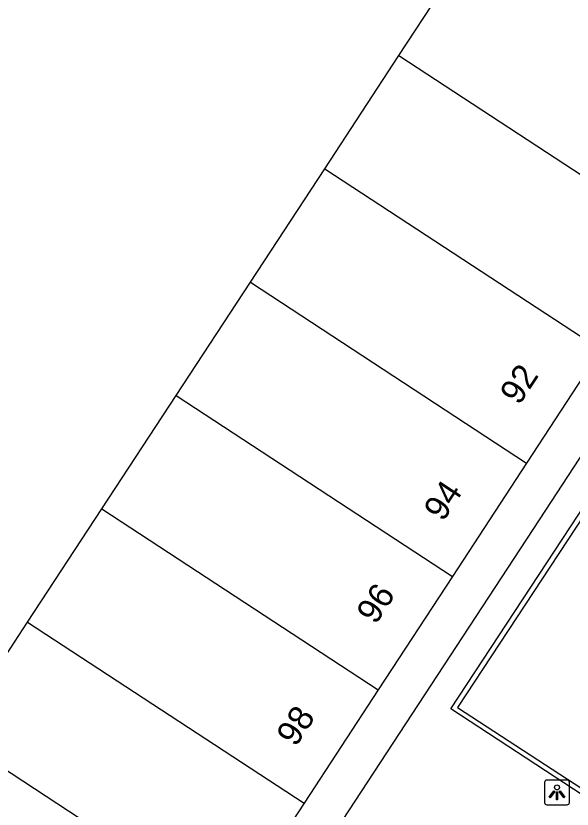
# Model space of a CAD drawing. Extents: x 155640 to 156810, y 382822 to 384046.
# Drawn here: x 156426.7 to 156449.06, y 383730.47 to 383762.35 of the extents above; entities that cross this region are included whole.
import ezdxf

# ---------------------------------------------------------------- set-up
doc = ezdxf.new("R2010")
doc.units = 0
for name, color, linetype in [('IMGEO_Lichtpunt', 7, 'Continuous'), ('IMGEO_Lijnafwatering', 7, 'Continuous'), ('IMGEO_Muur', 7, 'Continuous'), ('IMGEO_Pand', 7, 'Continuous'), ('IMGEO_Pand_nummerreeks', 7, 'Continuous')]:
    doc.layers.add(name, color=color, linetype=linetype)

msp = doc.modelspace()

# ---------------------------------------------------------------- linework, layer by layer
at = {"layer": 'IMGEO_Lichtpunt'}
for p, q in [((156447.949, 383731.548), (156447.949, 383730.741)), ((156447.949, 383731.548), (156447.949, 383730.741)), ((156448.851, 383731.643), (156448.043, 383731.643)), ((156448.851, 383731.643), (156448.043, 383731.643)), ((156448.945, 383730.741), (156448.945, 383731.548)), ((156448.945, 383730.741), (156448.945, 383731.548)), ((156448.043, 383730.647), (156448.851, 383730.647)), ((156448.043, 383730.647), (156448.851, 383730.647))]:
    msp.add_line(p, q, dxfattribs=at)
for points in [[(156448.323, 383731.212), (156448.362, 383731.184), (156448.174, 383730.922), (156448.136, 383730.949), (156448.323, 383731.212)], [(156448.535, 383731.184), (156448.573, 383731.211), (156448.76, 383730.949), (156448.721, 383730.921), (156448.535, 383731.184)], [(156448.425, 383731.164), (156448.472, 383731.164), (156448.472, 383730.842), (156448.425, 383730.842), (156448.425, 383731.164)]]:
    msp.add_lwpolyline(points, dxfattribs=at)
msp.add_circle((156448.448, 383731.346), 0.0994, dxfattribs=at)
for centre, start, end in [((156448.043, 383731.548), 90, 180), ((156448.043, 383731.548), 90, 180), ((156448.851, 383731.548), 0, 90), ((156448.851, 383731.548), 0, 90), ((156448.043, 383730.741), 180, 270), ((156448.043, 383730.741), 180, 270), ((156448.851, 383730.741), 270, 0), ((156448.851, 383730.741), 270, 360)]:
    msp.add_arc(centre, 0.0946, start, end, dxfattribs=at)
at = {"layer": 'IMGEO_Lijnafwatering'}
for points in [[(156460.088, 383760.982), (156447.726, 383742.098)], [(156447.726, 383742.098), (156436.226, 383724.532)]]:
    msp.add_lwpolyline(points, dxfattribs=at)
at = {"layer": 'IMGEO_Muur'}
for points in [[(156449.505, 383731.026), (156444.177, 383734.498), (156452.207, 383746.705), (156457.498, 383743.199), (156449.505, 383731.026)], [(156455.946, 383743.987), (156452.264, 383746.427), (156444.454, 383734.556), (156449.447, 383731.302), (156452.661, 383736.197)]]:
    msp.add_lwpolyline(points, dxfattribs=at)
at = {"layer": 'IMGEO_Pand'}
for points in [[(156442.097, 383760.76), (156445.081, 383765.315)], [(156439.113, 383756.204), (156442.097, 383760.76)], [(156442.097, 383760.76), (156453.187, 383753.496)], [(156436.129, 383751.648), (156439.113, 383756.204)], [(156439.113, 383756.204), (156450.206, 383748.938)], [(156433.145, 383747.093), (156436.129, 383751.648)], [(156436.129, 383751.648), (156447.225, 383744.38)], [(156450.206, 383748.938), (156447.225, 383744.38)], [(156430.161, 383742.537), (156433.145, 383747.093)], [(156433.145, 383747.093), (156444.244, 383739.822)], [(156447.225, 383744.38), (156444.244, 383739.822)], [(156427.177, 383737.982), (156430.161, 383742.537)], [(156430.161, 383742.537), (156441.264, 383735.265)], [(156444.244, 383739.822), (156441.264, 383735.265)], [(156424.193, 383733.426), (156427.177, 383737.982)], [(156427.177, 383737.982), (156438.283, 383730.707)], [(156441.264, 383735.265), (156438.283, 383730.707)], [(156424.193, 383733.426), (156435.302, 383726.149)], [(156438.283, 383730.707), (156435.302, 383726.149)]]:
    msp.add_lwpolyline(points, dxfattribs=at)

# ---------------------------------------------------------------- texts
at = {"layer": 'IMGEO_Pand_nummerreeks'}
for s, p in [('92', (156446.925, 383746.667)), ('94', (156443.866, 383741.99)), ('96', (156441.162, 383737.855)), ('98', (156437.947, 383732.939))]:
    msp.add_text(s, height=1, rotation=56.6197, dxfattribs=at).set_placement(p)

doc.saveas('drawing.dxf')
